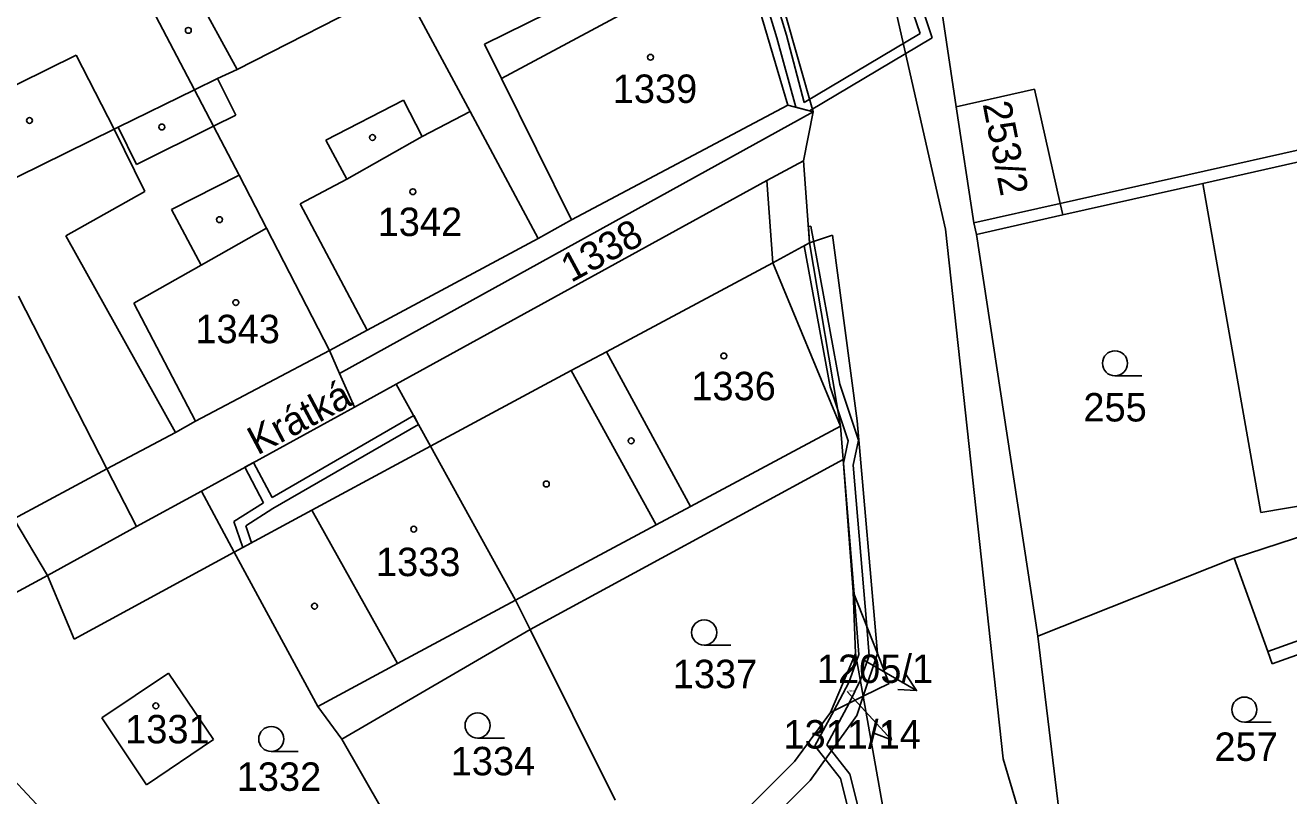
# Model space of a CAD drawing. Extents: x -785744 to -782822, y -1067550 to -1063910.
# Drawn here: x -783925.3 to -783849.7, y -1065402 to -1065355.9 of the extents above; entities that cross this region are included whole.
import ezdxf

# ---------------------------------------------------------------- set-up
doc = ezdxf.new("R2010")
doc.units = 0
for name, color, linetype in [('Hranice parcel', 7, 'Continuous'), ('Parcelní čísla', 7, 'Continuous'), ('Pop_ČP_popisy', 7, 'Continuous'), ('Vnitřní kresba', 7, 'Continuous'), ('Věcná břemena k části', 7, 'Continuous'), ('Značky budov', 7, 'Continuous'), ('Značky kultur', 7, 'Continuous')]:
    doc.layers.add(name, color=color, linetype=linetype)

msp = doc.modelspace()

# ---------------------------------------------------------------- linework, layer by layer
at = {"layer": 'Hranice parcel'}
for points in [[(-783882.43, -1065351.38), (-783879.67, -1065360.69)], [(-783902.72, -1065353.53), (-783898.67, -1065361.07)], [(-783917.9, -1065354.58), (-783915.17, -1065359.77)], [(-783912.6, -1065358.56), (-783903.54, -1065353.91)], [(-783870.51, -1065354.8), (-783869.6, -1065360.8)], [(-783915.17, -1065359.77), (-783913.78, -1065359.09)], [(-783913.78, -1065359.09), (-783912.6, -1065358.56)], [(-783919.73, -1065362.01), (-783915.17, -1065359.77)], [(-783915.17, -1065359.77), (-783914.02, -1065361.95)], [(-783869.6, -1065360.8), (-783864.92, -1065359.74)], [(-783864.92, -1065359.74), (-783863.39, -1065366.57)], [(-783892.61, -1065367.55), (-783879.67, -1065360.69)], [(-783879.67, -1065360.69), (-783878.16, -1065361.09)], [(-783898.67, -1065361.07), (-783894.6, -1065368.66)], [(-783878.73, -1065364.02), (-783878.16, -1065361.09)], [(-783869.6, -1065360.8), (-783868.55, -1065367.73)], [(-783928.63, -1065366.4), (-783919.97, -1065362.13)], [(-783919.97, -1065362.13), (-783919.73, -1065362.01)], [(-783914.02, -1065361.95), (-783912.49, -1065364.88)], [(-783880.94, -1065365.2), (-783878.73, -1065364.02)], [(-783878.73, -1065364.02), (-783878.37, -1065368.93)], [(-783854.85, -1065365.37), (-783848.06, -1065363.84)], [(-783912.49, -1065364.88), (-783910.85, -1065368.05)], [(-783903.09, -1065377.38), (-783880.94, -1065365.2)], [(-783863.23, -1065367.26), (-783854.85, -1065365.37)], [(-783854.85, -1065365.37), (-783851.95, -1065381.88)], [(-783863.39, -1065366.57), (-783863.23, -1065367.26)], [(-783868.4, -1065368.42), (-783863.23, -1065367.26)], [(-783910.85, -1065368.05), (-783907.09, -1065375.37)], [(-783894.6, -1065368.66), (-783892.61, -1065367.55)], [(-783868.55, -1065367.73), (-783868.4, -1065368.42)], [(-783904.84, -1065374.14), (-783894.6, -1065368.66)], [(-783880.58, -1065370.12), (-783878.37, -1065368.93)], [(-783868.4, -1065368.42), (-783864.73, -1065392.45)], [(-783880.58, -1065370.12), (-783876.52, -1065379.9)], [(-783925.69, -1065372.11), (-783920.4, -1065382.45)], [(-783907.09, -1065375.37), (-783904.84, -1065374.14)], [(-783907.09, -1065375.37), (-783906.48, -1065376.74)], [(-783906.48, -1065376.74), (-783905.59, -1065378.75)], [(-783905.59, -1065378.75), (-783903.09, -1065377.38)], [(-783903.09, -1065377.38), (-783901.05, -1065381.08)], [(-783914.75, -1065383.77), (-783905.59, -1065378.75)], [(-783876.52, -1065379.9), (-783876.36, -1065381.88)], [(-783901.05, -1065381.08), (-783895.97, -1065390.29)], [(-783920.4, -1065382.45), (-783918.63, -1065385.9)], [(-783895.08, -1065392.06), (-783876.36, -1065381.88)], [(-783876.36, -1065381.88), (-783875.77, -1065389.8)], [(-783851.95, -1065381.88), (-783851.39, -1065385.06)], [(-783918.63, -1065385.9), (-783914.75, -1065383.77)], [(-783914.75, -1065383.77), (-783912.78, -1065387.42)], [(-783851.39, -1065385.06), (-783848.32, -1065384.53)], [(-783923.95, -1065388.82), (-783918.63, -1065385.9)], [(-783852.98, -1065387.78), (-783848.51, -1065386.33)], [(-783912.78, -1065387.42), (-783907.78, -1065396.65)], [(-783864.73, -1065392.45), (-783852.98, -1065387.78)], [(-783852.98, -1065387.78), (-783850.96, -1065393.37)], [(-783932.89, -1065393.65), (-783923.95, -1065388.82)], [(-783875.77, -1065389.8), (-783875.62, -1065393.48)], [(-783875.77, -1065389.8), (-783874.32, -1065393.49)], [(-783895.97, -1065390.29), (-783895.08, -1065392.06)], [(-783906.35, -1065398.6), (-783895.08, -1065392.06)], [(-783895.08, -1065392.06), (-783890, -1065402.26)], [(-783864.73, -1065392.45), (-783863.01, -1065406.62)], [(-783850.7, -1065394.11), (-783846.41, -1065392.56)], [(-783932.89, -1065393.65), (-783918.29, -1065409.27)], [(-783877.13, -1065397.01), (-783875.62, -1065393.48)], [(-783875.62, -1065393.48), (-783875.16, -1065396.04)], [(-783874.32, -1065393.49), (-783873.62, -1065395.28)], [(-783850.96, -1065393.37), (-783850.7, -1065394.11)], [(-783920.7, -1065397.34), (-783916.72, -1065394.67)], [(-783916.72, -1065394.67), (-783914.03, -1065398.62)], [(-783875.16, -1065396.04), (-783873.62, -1065395.28)], [(-783877.13, -1065397.01), (-783875.16, -1065396.04)], [(-783875.16, -1065396.04), (-783873.19, -1065407.14)], [(-783907.78, -1065396.65), (-783906.35, -1065398.6)], [(-783920.7, -1065397.34), (-783918.04, -1065401.35)], [(-783879.28, -1065399.94), (-783877.13, -1065397.01)], [(-783918.04, -1065401.35), (-783914.03, -1065398.62)], [(-783906.35, -1065398.6), (-783903.91, -1065402.85)], [(-783887.22, -1065407.86), (-783879.28, -1065399.94)]]:
    msp.add_lwpolyline(points, dxfattribs=at)
at = {"layer": 'Pop_ČP_popisy'}
for p, q in [((-783874.57, -1065394.2), (-783871.972, -1065395.701)), ((-783875.5, -1065396.44), (-783873.48, -1065398.658))]:
    msp.add_line(p, q, dxfattribs=at)
for points in [[(-783875.19, -1065393.84), (-783874.57, -1065394.2)], [(-783872.588, -1065394.767), (-783871.972, -1065395.701), (-783873.088, -1065395.633)], [(-783876.12, -1065395.76), (-783875.5, -1065396.44)], [(-783873.784, -1065397.582), (-783873.48, -1065398.658), (-783874.523, -1065398.256)]]:
    msp.add_lwpolyline(points, dxfattribs=at)
at = {"layer": 'Vnitřní kresba'}
for points in [[(-783878.32, -1065332.59), (-783870.24, -1065368.1)], [(-783882.44, -1065346.03), (-783878.16, -1065361.09)], [(-783896.8, -1065359.1), (-783882.43, -1065351.38)], [(-783897.82, -1065357.05), (-783890.33, -1065353.33)], [(-783915.15, -1065353.91), (-783912.6, -1065358.56)], [(-783897.82, -1065357.05), (-783896.8, -1065359.1)], [(-783930.86, -1065361.95), (-783922.24, -1065357.71)], [(-783922.24, -1065357.71), (-783919.97, -1065362.13)], [(-783913.78, -1065359.09), (-783912.68, -1065361.3)], [(-783896.8, -1065359.1), (-783892.61, -1065367.55)], [(-783907.31, -1065362.79), (-783902.67, -1065360.39)], [(-783902.67, -1065360.39), (-783901.54, -1065362.56)], [(-783914.02, -1065361.95), (-783912.68, -1065361.3)], [(-783906.48, -1065376.74), (-783878.16, -1065361.09)], [(-783901.54, -1065362.56), (-783898.67, -1065361.07)], [(-783919.97, -1065362.13), (-783918.14, -1065365.85)], [(-783919.73, -1065362.01), (-783918.63, -1065364.25)], [(-783918.63, -1065364.25), (-783914.02, -1065361.95)], [(-783907.31, -1065362.79), (-783906.06, -1065365.11)], [(-783906.06, -1065365.11), (-783901.54, -1065362.56)], [(-783863.39, -1065366.57), (-783848.11, -1065363.14)], [(-783916.54, -1065366.94), (-783912.49, -1065364.88)], [(-783908.85, -1065366.6), (-783906.06, -1065365.11)], [(-783880.94, -1065365.2), (-783880.58, -1065370.12)], [(-783922.86, -1065368.5), (-783918.14, -1065365.85)], [(-783908.85, -1065366.6), (-783904.84, -1065374.14)], [(-783868.55, -1065367.73), (-783863.39, -1065366.57)], [(-783916.54, -1065366.94), (-783914.76, -1065370.26)], [(-783914.76, -1065370.26), (-783910.85, -1065368.05)], [(-783870.24, -1065368.1), (-783866.79, -1065399.79)], [(-783922.86, -1065368.5), (-783916.29, -1065380.26)], [(-783878.37, -1065368.93), (-783877.01, -1065368.47)], [(-783878.37, -1065368.93), (-783876.52, -1065379.9)], [(-783877.01, -1065368.47), (-783875.53, -1065379.57)], [(-783918.79, -1065372.54), (-783914.76, -1065370.26)], [(-783890.53, -1065375.44), (-783880.58, -1065370.12)], [(-783918.79, -1065372.54), (-783915.1, -1065379.6)], [(-783915.1, -1065379.6), (-783907.09, -1065375.37)], [(-783892.63, -1065376.57), (-783890.53, -1065375.44)], [(-783890.53, -1065375.44), (-783885.5, -1065384.69)], [(-783901.05, -1065381.08), (-783892.63, -1065376.57)], [(-783892.63, -1065376.57), (-783887.55, -1065385.79)], [(-783916.29, -1065380.26), (-783915.1, -1065379.6)], [(-783875.53, -1065379.57), (-783874.32, -1065393.49)], [(-783920.4, -1065382.45), (-783916.29, -1065380.26)], [(-783885.5, -1065384.69), (-783876.52, -1065379.9)], [(-783908.15, -1065384.92), (-783901.05, -1065381.08)], [(-783925.97, -1065385.43), (-783920.4, -1065382.45)], [(-783887.55, -1065385.79), (-783885.5, -1065384.69)], [(-783925.97, -1065385.43), (-783923.95, -1065388.82)], [(-783912.78, -1065387.42), (-783908.15, -1065384.92)], [(-783908.15, -1065384.92), (-783903.02, -1065394.09)], [(-783895.97, -1065390.29), (-783887.55, -1065385.79)], [(-783922.35, -1065392.62), (-783912.78, -1065387.42)], [(-783923.95, -1065388.82), (-783922.35, -1065392.62)], [(-783903.02, -1065394.09), (-783895.97, -1065390.29)], [(-783850.96, -1065393.37), (-783846.68, -1065391.83)], [(-783875.16, -1065396.04), (-783874.32, -1065393.49)], [(-783907.78, -1065396.65), (-783903.02, -1065394.09)], [(-783875.55, -1065397.2), (-783875.16, -1065396.04)], [(-783878.34, -1065401.09), (-783875.55, -1065397.2)], [(-783866.79, -1065399.79), (-783863.21, -1065411.89)], [(-783894.64, -1065417.41), (-783878.34, -1065401.09)]]:
    msp.add_lwpolyline(points, dxfattribs=at)
at = {"layer": 'Věcná břemena k části'}
for points in [[(-783887.49, -1065333.13), (-783880.33, -1065356.66)], [(-783879.75, -1065356.5), (-783886.91, -1065332.95)], [(-783872.37, -1065354.62), (-783871.77, -1065356.4)], [(-783871.05, -1065356.66), (-783871.71, -1065354.7)], [(-783880.33, -1065356.66), (-783879.2, -1065360.81)], [(-783878.69, -1065360.53), (-783879.75, -1065356.5)], [(-783871.77, -1065356.4), (-783878.69, -1065360.53)], [(-783878.37, -1065361.03), (-783871.05, -1065356.66)], [(-783879.2, -1065360.81), (-783878.37, -1065361.03)], [(-783878.3, -1065367.93), (-783878.44, -1065367.94), (-783878.37, -1065368.93)], [(-783876.57, -1065377.37), (-783878.3, -1065367.93)], [(-783878.37, -1065368.93), (-783878.7, -1065369.11)], [(-783878.7, -1065369.11), (-783877.15, -1065377.53)], [(-783877.15, -1065377.53), (-783876.06, -1065380.77)], [(-783875.44, -1065380.73), (-783876.57, -1065377.37)], [(-783902.05, -1065379.26), (-783910.51, -1065384.16)], [(-783901.76, -1065379.79), (-783902.05, -1065379.26)], [(-783910.47, -1065384.82), (-783901.76, -1065379.79)], [(-783876.06, -1065380.77), (-783876.34, -1065382.1)], [(-783875.76, -1065382.23), (-783875.44, -1065380.73)], [(-783911.63, -1065382.06), (-783912.16, -1065382.35)], [(-783912.16, -1065382.35), (-783911.03, -1065384.47)], [(-783910.51, -1065384.16), (-783911.63, -1065382.06)], [(-783876.34, -1065382.1), (-783875.71, -1065389.94)], [(-783874.96, -1065391.86), (-783875.76, -1065382.23)], [(-783911.03, -1065384.47), (-783912.81, -1065385.6)], [(-783912.09, -1065385.86), (-783910.47, -1065384.82)], [(-783912.81, -1065385.6), (-783912.28, -1065387.15)], [(-783911.76, -1065386.87), (-783912.09, -1065385.86)], [(-783912.28, -1065387.15), (-783911.76, -1065386.87)], [(-783875.71, -1065389.94), (-783875.42, -1065393.54)], [(-783876.01, -1065396.46), (-783875.33, -1065395.07), (-783874.82, -1065393.62), (-783874.96, -1065391.86)], [(-783875.42, -1065393.54), (-783875.55, -1065393.89), (-783876.02, -1065395.23), (-783876.93, -1065396.91)], [(-783876.93, -1065396.91), (-783878.06, -1065399)], [(-783877.34, -1065398.94), (-783876.01, -1065396.46)], [(-783878.06, -1065399), (-783876.52, -1065400.97)], [(-783875.96, -1065400.71), (-783877.34, -1065398.94)], [(-783874.2, -1065407.73), (-783875.96, -1065400.71)], [(-783876.52, -1065400.97), (-783874.73, -1065408.1)]]:
    msp.add_lwpolyline(points, dxfattribs=at)
at = {"layer": 'Značky budov'}
for centre in [(-783915.53, -1065356.22), (-783887.89, -1065357.83), (-783925.03, -1065361.61), (-783917.11, -1065362), (-783904.52, -1065362.63), (-783902.1, -1065365.87), (-783913.67, -1065367.54), (-783912.69, -1065372.5), (-783883.5, -1065375.69), (-783889.05, -1065380.77), (-783894.12, -1065383.35), (-783902.05, -1065386.05), (-783907.98, -1065390.66), (-783917.47, -1065396.62)]:
    msp.add_circle(centre, 0.175, dxfattribs=at)
at = {"layer": 'Značky kultur'}
for p, q in [((-783860.11, -1065376.88), (-783858.51, -1065376.88)), ((-783884.68, -1065392.98), (-783883.08, -1065392.98)), ((-783852.37, -1065397.59), (-783850.77, -1065397.59)), ((-783898.23, -1065398.54), (-783896.63, -1065398.54)), ((-783910.57, -1065399.35), (-783908.97, -1065399.35))]:
    msp.add_line(p, q, dxfattribs=at)
for centre in [(-783860.11, -1065376.13), (-783884.68, -1065392.23), (-783852.37, -1065396.84), (-783898.23, -1065397.79), (-783910.57, -1065398.6)]:
    msp.add_circle(centre, 0.75, dxfattribs=at)

# ---------------------------------------------------------------- texts
at = {"layer": 'Parcelní čísla'}
for s, height, p in [('1339', 1.7, (-783890.15, -1065360.56)), ('1342', 1.7, (-783904.21, -1065368.52)), ('1343', 1.7, (-783915.11, -1065374.93)), ('1336', 1.7, (-783885.45, -1065378.34)), ('255', 1.7, (-783862, -1065379.61)), ('1333', 1.7, (-783904.31, -1065388.86)), ('1337', 1.7, (-783886.56, -1065395.56)), ('1205/1', 0.1, (-783875.19, -1065393.84)), ('1311/14', 0.1, (-783876.12, -1065395.76)), ('1331', 1.7, (-783919.31, -1065398.86)), ('257', 1.7, (-783854.16, -1065399.91)), ('1334', 1.7, (-783899.84, -1065400.77)), ('1332', 1.7, (-783912.64, -1065401.7))]:
    msp.add_text(s, height=height, dxfattribs=at).set_placement(p)
for s, rotation, p in [('253/2', 281.18655, (-783868.03, -1065360.62)), ('1338', 28.41957, (-783892.64, -1065371.33))]:
    msp.add_text(s, height=1.7, rotation=rotation, dxfattribs=at).set_placement(p)
at = {"layer": 'Pop_ČP_popisy'}
msp.add_text('Krátká', height=1.7, rotation=27.9612, dxfattribs=at).set_placement((-783911.4, -1065381.65))
for s, p in [('1205/1', (-783877.937, -1065395.25)), ('1311/14', (-783879.938, -1065399.17))]:
    msp.add_text(s, height=1.7, dxfattribs=at).set_placement(p)

doc.saveas('drawing.dxf')
